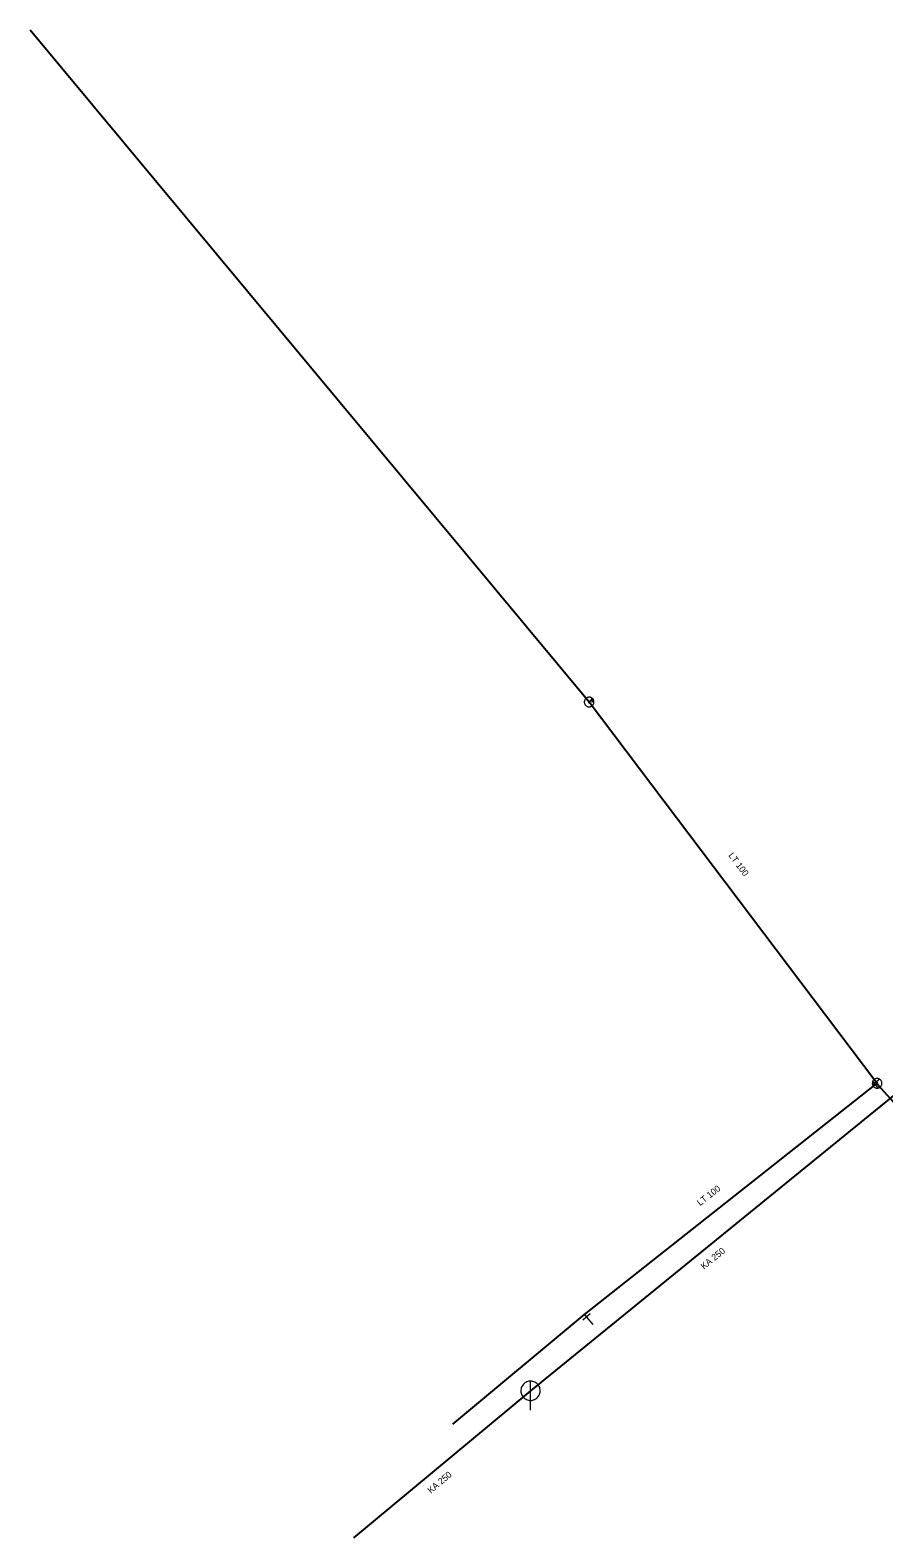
# Model space of a CAD drawing. Extents: x -688296 to -687852, y -973332 to -972816.
# Drawn here: x -688295.7 to -688207.2, y -973182.9 to -973026.7 of the extents above; entities that cross this region are included whole.
import ezdxf
from ezdxf.enums import TextEntityAlignment as Align

# ---------------------------------------------------------------- set-up
doc = ezdxf.new("R2010")
doc.units = 0
doc.header["$LTSCALE"] = 0.27
for name, color, linetype, lineweight in [('1', 7, 'Continuous', 25), ('13', 7, 'Continuous', 13), ('14', 7, 'Continuous', 13), ('17', 7, 'Continuous', 25), ('22', 7, 'Continuous', 13), ('34', 7, 'Continuous', 13), ('47', 7, 'Continuous', 13), ('9', 7, 'Continuous', 13)]:
    doc.layers.add(name, color=color, linetype=linetype, lineweight=lineweight)

msp = doc.modelspace()

# ---------------------------------------------------------------- linework, layer by layer
at = {"layer": '13'}
msp.add_line((-688238.059, -973160.05), (-688237.39, -973160.82), dxfattribs=at)
at = {"layer": '14'}
for p, q in [((-688237.458, -973096.095), (-688237.776, -973096.338)), ((-688238.27, -973159.789), (-688238.059, -973160.05))]:
    msp.add_line(p, q, dxfattribs=at)
at = {"layer": '14', "lineweight": 25}
for p, q in [((-688205.548, -973136.535), (-688243.846, -973167.688)), ((-688243.846, -973167.688), (-688262.193, -973182.927))]:
    msp.add_line(p, q, dxfattribs=at)
at = {"layer": '14'}
msp.add_lwpolyline([(-688208.16, -973135.989), (-688207.94, -973135.84), (-688208.07, -973135.69)], dxfattribs=at)
at = {"layer": '17'}
for p, q in [((-688237.776, -973096.338), (-688295.678, -973026.728)), ((-688208.07, -973135.69), (-688237.776, -973096.338))]:
    msp.add_line(p, q, dxfattribs=at)
for points in [[(-688251.899, -973171.14), (-688238.27, -973159.789), (-688208.16, -973135.989)], [(-688207.94, -973135.84), (-688207.62, -973136.28), (-688207.559, -973136.35), (-688204.879, -973139.32)]]:
    msp.add_lwpolyline(points, dxfattribs=at)
at = {"layer": '22'}
msp.add_line((-688243.846, -973169.688), (-688243.845, -973166.688), dxfattribs=at)
msp.add_lwpolyline([(-688242.846, -973167.688), (-688242.851, -973167.579), (-688242.869, -973167.471), (-688242.899, -973167.365), (-688242.939, -973167.264), (-688242.991, -973167.167), (-688243.053, -973167.077), (-688243.125, -973166.994), (-688243.205, -973166.92), (-688243.293, -973166.854), (-688243.387, -973166.799), (-688243.487, -973166.754), (-688243.592, -973166.721), (-688243.699, -973166.699), (-688243.808, -973166.689), (-688243.918, -973166.691), (-688244.026, -973166.705), (-688244.133, -973166.73), (-688244.236, -973166.767), (-688244.334, -973166.816), (-688244.426, -973166.874), (-688244.512, -973166.943), (-688244.589, -973167.02), (-688244.658, -973167.106), (-688244.717, -973167.198), (-688244.765, -973167.296), (-688244.802, -973167.399), (-688244.828, -973167.506), (-688244.842, -973167.614), (-688244.845, -973167.724), (-688244.835, -973167.833), (-688244.814, -973167.94), (-688244.78, -973168.044), (-688244.736, -973168.144), (-688244.681, -973168.239), (-688244.615, -973168.327), (-688244.541, -973168.407), (-688244.458, -973168.479), (-688244.368, -973168.541), (-688244.272, -973168.593), (-688244.17, -973168.634), (-688244.065, -973168.664), (-688243.957, -973168.682), (-688243.847, -973168.688), (-688243.738, -973168.682), (-688243.63, -973168.664), (-688243.525, -973168.635), (-688243.423, -973168.594), (-688243.326, -973168.542), (-688243.236, -973168.48), (-688243.153, -973168.409), (-688243.078, -973168.329), (-688243.013, -973168.241), (-688242.957, -973168.147), (-688242.913, -973168.047), (-688242.879, -973167.943), (-688242.857, -973167.835), (-688242.847, -973167.726)], close=True, dxfattribs=at)
at = {"layer": '34'}
for p, q in [((-688208.468, -973135.991), (-688207.67, -973135.389)), ((-688208.47, -973135.597), (-688207.85, -973136.381)), ((-688237.682, -973159.721), (-688238.436, -973160.377))]:
    msp.add_line(p, q, dxfattribs=at)
at = {"layer": '47'}
for points in [[(-688237.406, -973096), (-688237.444, -973095.964), (-688237.485, -973095.931), (-688237.529, -973095.903), (-688237.575, -973095.879), (-688237.624, -973095.861), (-688237.676, -973095.848), (-688237.727, -973095.841), (-688237.779, -973095.838), (-688237.831, -973095.841), (-688237.883, -973095.849), (-688237.934, -973095.863), (-688237.982, -973095.883), (-688238.029, -973095.906), (-688238.072, -973095.936), (-688238.113, -973095.968), (-688238.149, -973096.006), (-688238.182, -973096.047), (-688238.21, -973096.091), (-688238.234, -973096.137), (-688238.252, -973096.186), (-688238.265, -973096.238), (-688238.273, -973096.29), (-688238.275, -973096.342), (-688238.273, -973096.394), (-688238.264, -973096.445), (-688238.25, -973096.496), (-688238.231, -973096.545), (-688238.207, -973096.591), (-688238.177, -973096.634), (-688238.145, -973096.675), (-688238.107, -973096.711), (-688238.066, -973096.744), (-688238.022, -973096.773), (-688237.976, -973096.796), (-688237.927, -973096.814), (-688237.876, -973096.828), (-688237.824, -973096.836), (-688237.772, -973096.838), (-688237.719, -973096.835), (-688237.668, -973096.826), (-688237.617, -973096.812), (-688237.569, -973096.793), (-688237.522, -973096.769), (-688237.479, -973096.739), (-688237.438, -973096.707), (-688237.402, -973096.669), (-688237.369, -973096.628), (-688237.341, -973096.585), (-688237.317, -973096.538), (-688237.299, -973096.489), (-688237.285, -973096.438), (-688237.278, -973096.387), (-688237.276, -973096.335), (-688237.279, -973096.282), (-688237.287, -973096.23), (-688237.301, -973096.179), (-688237.32, -973096.132), (-688237.344, -973096.084), (-688237.374, -973096.041)], [(-688237.715, -973096.282), (-688237.721, -973096.276), (-688237.728, -973096.271), (-688237.735, -973096.266), (-688237.742, -973096.263), (-688237.751, -973096.259), (-688237.759, -973096.258), (-688237.768, -973096.256), (-688237.776, -973096.255), (-688237.785, -973096.256), (-688237.793, -973096.257), (-688237.802, -973096.26), (-688237.81, -973096.263), (-688237.817, -973096.267), (-688237.824, -973096.271), (-688237.831, -973096.277), (-688237.837, -973096.283), (-688237.842, -973096.29), (-688237.847, -973096.297), (-688237.85, -973096.304), (-688237.854, -973096.313), (-688237.855, -973096.321), (-688237.857, -973096.33), (-688237.858, -973096.338), (-688237.857, -973096.347), (-688237.856, -973096.355), (-688237.853, -973096.364), (-688237.85, -973096.372), (-688237.846, -973096.379), (-688237.842, -973096.386), (-688237.836, -973096.393), (-688237.83, -973096.399), (-688237.823, -973096.404), (-688237.816, -973096.409), (-688237.809, -973096.412), (-688237.8, -973096.416), (-688237.793, -973096.418), (-688237.783, -973096.419), (-688237.775, -973096.42), (-688237.766, -973096.419), (-688237.758, -973096.418), (-688237.749, -973096.415), (-688237.741, -973096.412), (-688237.734, -973096.408), (-688237.727, -973096.404), (-688237.72, -973096.398), (-688237.714, -973096.392), (-688237.709, -973096.385), (-688237.704, -973096.378), (-688237.701, -973096.371), (-688237.697, -973096.362), (-688237.695, -973096.355), (-688237.694, -973096.345), (-688237.693, -973096.337), (-688237.694, -973096.328), (-688237.695, -973096.32), (-688237.698, -973096.311), (-688237.701, -973096.303), (-688237.705, -973096.296), (-688237.709, -973096.289)], [(-688207.645, -973136.244), (-688207.605, -973136.211), (-688207.568, -973136.174), (-688207.536, -973136.133), (-688207.507, -973136.09), (-688207.483, -973136.043), (-688207.464, -973135.993), (-688207.451, -973135.943), (-688207.443, -973135.891), (-688207.44, -973135.84), (-688207.442, -973135.787), (-688207.451, -973135.735), (-688207.465, -973135.685), (-688207.483, -973135.636), (-688207.507, -973135.589), (-688207.535, -973135.545), (-688207.568, -973135.505), (-688207.605, -973135.468), (-688207.647, -973135.435), (-688207.689, -973135.407), (-688207.736, -973135.383), (-688207.786, -973135.364), (-688207.836, -973135.35), (-688207.888, -973135.342), (-688207.94, -973135.339), (-688207.992, -973135.342), (-688208.044, -973135.351), (-688208.095, -973135.364), (-688208.143, -973135.383), (-688208.19, -973135.407), (-688208.234, -973135.435), (-688208.274, -973135.468), (-688208.311, -973135.505), (-688208.345, -973135.546), (-688208.372, -973135.589), (-688208.396, -973135.636), (-688208.415, -973135.685), (-688208.429, -973135.736), (-688208.437, -973135.787), (-688208.44, -973135.84), (-688208.437, -973135.892), (-688208.428, -973135.944), (-688208.416, -973135.994), (-688208.396, -973136.043), (-688208.372, -973136.09), (-688208.344, -973136.134), (-688208.311, -973136.174), (-688208.274, -973136.211), (-688208.234, -973136.244), (-688208.19, -973136.272), (-688208.143, -973136.296), (-688208.094, -973136.315), (-688208.044, -973136.328), (-688207.992, -973136.337), (-688207.94, -973136.339), (-688207.887, -973136.337), (-688207.835, -973136.328), (-688207.785, -973136.315), (-688207.736, -973136.296), (-688207.689, -973136.272)], [(-688207.891, -973135.906), (-688207.884, -973135.901), (-688207.879, -973135.894), (-688207.873, -973135.888), (-688207.869, -973135.881), (-688207.865, -973135.873), (-688207.862, -973135.865), (-688207.859, -973135.856), (-688207.858, -973135.848), (-688207.858, -973135.84), (-688207.858, -973135.831), (-688207.859, -973135.822), (-688207.862, -973135.814), (-688207.865, -973135.806), (-688207.868, -973135.799), (-688207.873, -973135.791), (-688207.878, -973135.784), (-688207.885, -973135.779), (-688207.891, -973135.773), (-688207.898, -973135.769), (-688207.906, -973135.765), (-688207.914, -973135.762), (-688207.923, -973135.759), (-688207.931, -973135.758), (-688207.94, -973135.757), (-688207.948, -973135.758), (-688207.957, -973135.759), (-688207.965, -973135.762), (-688207.973, -973135.765), (-688207.98, -973135.768), (-688207.988, -973135.773), (-688207.995, -973135.778), (-688208, -973135.785), (-688208.006, -973135.791), (-688208.01, -973135.798), (-688208.014, -973135.806), (-688208.018, -973135.814), (-688208.02, -973135.823), (-688208.021, -973135.831), (-688208.022, -973135.84), (-688208.021, -973135.848), (-688208.02, -973135.857), (-688208.017, -973135.865), (-688208.014, -973135.873), (-688208.011, -973135.88), (-688208.006, -973135.888), (-688208.001, -973135.895), (-688207.994, -973135.9), (-688207.988, -973135.906), (-688207.981, -973135.91), (-688207.973, -973135.914), (-688207.965, -973135.918), (-688207.956, -973135.92), (-688207.948, -973135.921), (-688207.94, -973135.921), (-688207.931, -973135.921), (-688207.922, -973135.92), (-688207.914, -973135.917), (-688207.906, -973135.914), (-688207.899, -973135.911)]]:
    msp.add_lwpolyline(points, close=True, dxfattribs=at)
at = {"layer": '9'}
msp.add_line((-688237.459, -973096.222), (-688237.459, -973096.347), dxfattribs=at)
for points in [[(-688237.585, -973096.094), (-688237.584, -973096.107), (-688237.582, -973096.12), (-688237.579, -973096.133), (-688237.574, -973096.145), (-688237.568, -973096.157), (-688237.561, -973096.168), (-688237.553, -973096.178), (-688237.543, -973096.188), (-688237.533, -973096.196), (-688237.522, -973096.203), (-688237.51, -973096.209), (-688237.498, -973096.214), (-688237.485, -973096.217), (-688237.472, -973096.219), (-688237.459, -973096.222), (-688237.446, -973096.221), (-688237.433, -973096.219), (-688237.42, -973096.216), (-688237.408, -973096.211), (-688237.396, -973096.205), (-688237.385, -973096.198), (-688237.375, -973096.19), (-688237.365, -973096.18), (-688237.357, -973096.17), (-688237.35, -973096.159), (-688237.344, -973096.147), (-688237.339, -973096.135), (-688237.336, -973096.122), (-688237.334, -973096.109), (-688237.332, -973096.096), (-688237.333, -973096.083), (-688237.335, -973096.07), (-688237.338, -973096.057), (-688237.343, -973096.045), (-688237.349, -973096.033), (-688237.356, -973096.022), (-688237.364, -973096.012), (-688237.374, -973096.002), (-688237.384, -973095.994), (-688237.395, -973095.987), (-688237.407, -973095.981), (-688237.419, -973095.976), (-688237.432, -973095.973), (-688237.445, -973095.971), (-688237.458, -973095.968), (-688237.471, -973095.969), (-688237.484, -973095.971), (-688237.497, -973095.974), (-688237.509, -973095.979), (-688237.521, -973095.985), (-688237.532, -973095.992), (-688237.542, -973096), (-688237.552, -973096.01), (-688237.56, -973096.02), (-688237.567, -973096.031), (-688237.573, -973096.043), (-688237.578, -973096.055), (-688237.581, -973096.068), (-688237.583, -973096.081)], [(-688237.565, -973096.094), (-688237.565, -973096.105), (-688237.563, -973096.116), (-688237.56, -973096.127), (-688237.556, -973096.137), (-688237.551, -973096.147), (-688237.545, -973096.156), (-688237.538, -973096.165), (-688237.53, -973096.173), (-688237.521, -973096.18), (-688237.512, -973096.186), (-688237.502, -973096.191), (-688237.492, -973096.195), (-688237.481, -973096.198), (-688237.47, -973096.2), (-688237.459, -973096.2), (-688237.448, -973096.202), (-688237.437, -973096.2), (-688237.426, -973096.197), (-688237.416, -973096.193), (-688237.406, -973096.188), (-688237.397, -973096.182), (-688237.388, -973096.175), (-688237.38, -973096.167), (-688237.373, -973096.158), (-688237.367, -973096.149), (-688237.362, -973096.139), (-688237.358, -973096.129), (-688237.355, -973096.118), (-688237.353, -973096.107), (-688237.352, -973096.096), (-688237.352, -973096.085), (-688237.354, -973096.074), (-688237.357, -973096.063), (-688237.361, -973096.053), (-688237.366, -973096.043), (-688237.372, -973096.034), (-688237.379, -973096.025), (-688237.387, -973096.017), (-688237.396, -973096.01), (-688237.405, -973096.004), (-688237.415, -973095.999), (-688237.425, -973095.995), (-688237.436, -973095.992), (-688237.447, -973095.99), (-688237.458, -973095.989), (-688237.469, -973095.988), (-688237.48, -973095.99), (-688237.491, -973095.993), (-688237.501, -973095.997), (-688237.511, -973096.002), (-688237.52, -973096.008), (-688237.529, -973096.015), (-688237.537, -973096.023), (-688237.544, -973096.032), (-688237.55, -973096.041), (-688237.555, -973096.051), (-688237.559, -973096.061), (-688237.562, -973096.072), (-688237.564, -973096.083)], [(-688237.546, -973096.094), (-688237.545, -973096.103), (-688237.544, -973096.112), (-688237.541, -973096.121), (-688237.538, -973096.129), (-688237.534, -973096.137), (-688237.529, -973096.145), (-688237.523, -973096.152), (-688237.517, -973096.158), (-688237.51, -973096.164), (-688237.502, -973096.169), (-688237.494, -973096.173), (-688237.486, -973096.176), (-688237.477, -973096.179), (-688237.468, -973096.18), (-688237.459, -973096.183), (-688237.45, -973096.182), (-688237.441, -973096.181), (-688237.432, -973096.178), (-688237.424, -973096.175), (-688237.416, -973096.171), (-688237.408, -973096.166), (-688237.401, -973096.16), (-688237.395, -973096.154), (-688237.389, -973096.147), (-688237.384, -973096.139), (-688237.38, -973096.131), (-688237.377, -973096.123), (-688237.374, -973096.114), (-688237.373, -973096.105), (-688237.371, -973096.096), (-688237.372, -973096.087), (-688237.373, -973096.078), (-688237.376, -973096.069), (-688237.379, -973096.061), (-688237.383, -973096.053), (-688237.388, -973096.045), (-688237.394, -973096.038), (-688237.4, -973096.032), (-688237.407, -973096.026), (-688237.415, -973096.021), (-688237.423, -973096.017), (-688237.431, -973096.014), (-688237.44, -973096.011), (-688237.449, -973096.01), (-688237.458, -973096.007), (-688237.467, -973096.008), (-688237.476, -973096.009), (-688237.485, -973096.012), (-688237.493, -973096.015), (-688237.501, -973096.019), (-688237.509, -973096.024), (-688237.516, -973096.03), (-688237.522, -973096.036), (-688237.528, -973096.043), (-688237.533, -973096.051), (-688237.537, -973096.059), (-688237.54, -973096.067), (-688237.543, -973096.076), (-688237.544, -973096.085)], [(-688237.526, -973096.094), (-688237.526, -973096.101), (-688237.524, -973096.108), (-688237.523, -973096.115), (-688237.52, -973096.121), (-688237.517, -973096.127), (-688237.513, -973096.133), (-688237.509, -973096.139), (-688237.504, -973096.144), (-688237.498, -973096.148), (-688237.492, -973096.152), (-688237.486, -973096.155), (-688237.48, -973096.158), (-688237.473, -973096.159), (-688237.466, -973096.161), (-688237.459, -973096.161), (-688237.452, -973096.163), (-688237.445, -973096.161), (-688237.438, -973096.16), (-688237.432, -973096.157), (-688237.425, -973096.154), (-688237.42, -973096.15), (-688237.414, -973096.146), (-688237.409, -973096.141), (-688237.405, -973096.135), (-688237.401, -973096.129), (-688237.398, -973096.123), (-688237.395, -973096.117), (-688237.393, -973096.11), (-688237.392, -973096.103), (-688237.391, -973096.096), (-688237.391, -973096.089), (-688237.392, -973096.082), (-688237.394, -973096.075), (-688237.397, -973096.069), (-688237.4, -973096.062), (-688237.404, -973096.057), (-688237.408, -973096.051), (-688237.413, -973096.046), (-688237.419, -973096.042), (-688237.424, -973096.038), (-688237.431, -973096.035), (-688237.437, -973096.032), (-688237.444, -973096.03), (-688237.451, -973096.029), (-688237.458, -973096.027), (-688237.465, -973096.027), (-688237.472, -973096.028), (-688237.479, -973096.03), (-688237.485, -973096.033), (-688237.491, -973096.036), (-688237.497, -973096.04), (-688237.503, -973096.044), (-688237.508, -973096.049), (-688237.512, -973096.055), (-688237.516, -973096.06), (-688237.519, -973096.067), (-688237.522, -973096.073), (-688237.523, -973096.08), (-688237.525, -973096.087)], [(-688237.506, -973096.094), (-688237.506, -973096.099), (-688237.505, -973096.104), (-688237.504, -973096.109), (-688237.502, -973096.113), (-688237.5, -973096.118), (-688237.497, -973096.122), (-688237.494, -973096.125), (-688237.49, -973096.129), (-688237.487, -973096.132), (-688237.483, -973096.135), (-688237.478, -973096.137), (-688237.474, -973096.139), (-688237.469, -973096.14), (-688237.464, -973096.141), (-688237.459, -973096.141), (-688237.454, -973096.143), (-688237.449, -973096.142), (-688237.444, -973096.141), (-688237.44, -973096.139), (-688237.435, -973096.137), (-688237.431, -973096.134), (-688237.427, -973096.131), (-688237.424, -973096.127), (-688237.421, -973096.124), (-688237.418, -973096.12), (-688237.416, -973096.115), (-688237.414, -973096.111), (-688237.413, -973096.106), (-688237.412, -973096.101), (-688237.412, -973096.096), (-688237.411, -973096.091), (-688237.412, -973096.086), (-688237.413, -973096.081), (-688237.415, -973096.077), (-688237.417, -973096.072), (-688237.42, -973096.068), (-688237.423, -973096.064), (-688237.426, -973096.061), (-688237.43, -973096.058), (-688237.434, -973096.055), (-688237.439, -973096.053), (-688237.443, -973096.051), (-688237.448, -973096.05), (-688237.453, -973096.049), (-688237.458, -973096.048), (-688237.463, -973096.047), (-688237.468, -973096.048), (-688237.473, -973096.049), (-688237.477, -973096.051), (-688237.482, -973096.053), (-688237.486, -973096.056), (-688237.489, -973096.059), (-688237.493, -973096.062), (-688237.496, -973096.066), (-688237.499, -973096.07), (-688237.501, -973096.075), (-688237.503, -973096.079), (-688237.504, -973096.084), (-688237.505, -973096.089)], [(-688237.486, -973096.094), (-688237.486, -973096.097), (-688237.486, -973096.1), (-688237.485, -973096.102), (-688237.484, -973096.105), (-688237.483, -973096.108), (-688237.481, -973096.11), (-688237.479, -973096.112), (-688237.477, -973096.114), (-688237.475, -973096.116), (-688237.473, -973096.118), (-688237.47, -973096.119), (-688237.467, -973096.12), (-688237.465, -973096.121), (-688237.462, -973096.121), (-688237.459, -973096.121), (-688237.456, -973096.123), (-688237.453, -973096.123), (-688237.45, -973096.122), (-688237.448, -973096.121), (-688237.445, -973096.12), (-688237.443, -973096.118), (-688237.44, -973096.116), (-688237.438, -973096.114), (-688237.437, -973096.112), (-688237.435, -973096.11), (-688237.434, -973096.107), (-688237.433, -973096.104), (-688237.432, -973096.102), (-688237.432, -973096.099), (-688237.43, -973096.096), (-688237.431, -973096.093), (-688237.431, -973096.09), (-688237.432, -973096.087), (-688237.433, -973096.085), (-688237.434, -973096.082), (-688237.436, -973096.08), (-688237.437, -973096.077), (-688237.439, -973096.075), (-688237.442, -973096.074), (-688237.444, -973096.072), (-688237.447, -973096.071), (-688237.449, -973096.07), (-688237.452, -973096.069), (-688237.455, -973096.069), (-688237.458, -973096.066), (-688237.461, -973096.067), (-688237.464, -973096.067), (-688237.466, -973096.068), (-688237.469, -973096.069), (-688237.472, -973096.07), (-688237.474, -973096.072), (-688237.476, -973096.073), (-688237.478, -973096.075), (-688237.48, -973096.078), (-688237.482, -973096.08), (-688237.483, -973096.083), (-688237.484, -973096.085), (-688237.485, -973096.088), (-688237.485, -973096.091)], [(-688237.467, -973096.094), (-688237.467, -973096.095), (-688237.467, -973096.096), (-688237.466, -973096.096), (-688237.466, -973096.097), (-688237.466, -973096.098), (-688237.465, -973096.099), (-688237.465, -973096.099), (-688237.464, -973096.1), (-688237.464, -973096.1), (-688237.463, -973096.101), (-688237.462, -973096.101), (-688237.461, -973096.101), (-688237.461, -973096.102), (-688237.46, -973096.102), (-688237.459, -973096.102), (-688237.458, -973096.103), (-688237.457, -973096.103), (-688237.457, -973096.103), (-688237.456, -973096.103), (-688237.455, -973096.103), (-688237.454, -973096.102), (-688237.454, -973096.102), (-688237.453, -973096.101), (-688237.453, -973096.101), (-688237.452, -973096.1), (-688237.452, -973096.099), (-688237.451, -973096.098), (-688237.451, -973096.098), (-688237.451, -973096.097), (-688237.45, -973096.096), (-688237.45, -973096.095), (-688237.45, -973096.094), (-688237.45, -973096.094), (-688237.451, -973096.093), (-688237.451, -973096.092), (-688237.452, -973096.091), (-688237.452, -973096.091), (-688237.453, -973096.09), (-688237.453, -973096.09), (-688237.454, -973096.089), (-688237.455, -973096.089), (-688237.456, -973096.088), (-688237.456, -973096.088), (-688237.457, -973096.088), (-688237.458, -973096.087), (-688237.459, -973096.087), (-688237.46, -973096.086), (-688237.46, -973096.086), (-688237.461, -973096.087), (-688237.462, -973096.087), (-688237.463, -973096.088), (-688237.463, -973096.088), (-688237.464, -973096.089), (-688237.464, -973096.089), (-688237.465, -973096.09), (-688237.465, -973096.091), (-688237.465, -973096.092), (-688237.466, -973096.092), (-688237.466, -973096.093)]]:
    msp.add_lwpolyline(points, close=True, dxfattribs=at)
msp.add_lwpolyline([(-688237.428, -973096.313), (-688237.459, -973096.347), (-688237.49, -973096.311)], dxfattribs=at)

# ---------------------------------------------------------------- texts
at = {"layer": '1'}
for s, rotation, p in [('LT 100', 307, (-688222.5517, -973113.3441)), ('LT 100', 307, (-688222.5517, -973113.3441)), ('LT 100', 307, (-688222.5517, -973113.3441)), ('LT 100', 307, (-688222.5517, -973113.3441)), ('LT 100', 307, (-688222.5517, -973113.3441)), ('LT 100', 38, (-688225.1907, -973147.7164)), ('LT 100', 38, (-688225.1907, -973147.7164)), ('LT 100', 38, (-688225.1907, -973147.7164)), ('LT 100', 38, (-688225.1907, -973147.7164)), ('LT 100', 38, (-688225.1907, -973147.7164)), ('KA 250', 39, (-688224.7492, -973154.2317)), ('KA 250', 39, (-688224.7492, -973154.2317)), ('KA 250', 39, (-688224.7492, -973154.2317)), ('KA 250', 39, (-688224.7492, -973154.2317)), ('KA 250', 39, (-688224.7492, -973154.2317)), ('KA 250', 40, (-688253.0575, -973177.4269)), ('KA 250', 40, (-688253.0575, -973177.4269)), ('KA 250', 40, (-688253.0575, -973177.4269)), ('KA 250', 40, (-688253.0575, -973177.4269)), ('KA 250', 40, (-688253.0575, -973177.4269))]:
    msp.add_text(s, height=0.6667, rotation=rotation, dxfattribs=at).set_placement(p, align=Align.CENTER)

doc.saveas('drawing.dxf')
